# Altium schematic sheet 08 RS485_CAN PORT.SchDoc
size 420 x 297 mm
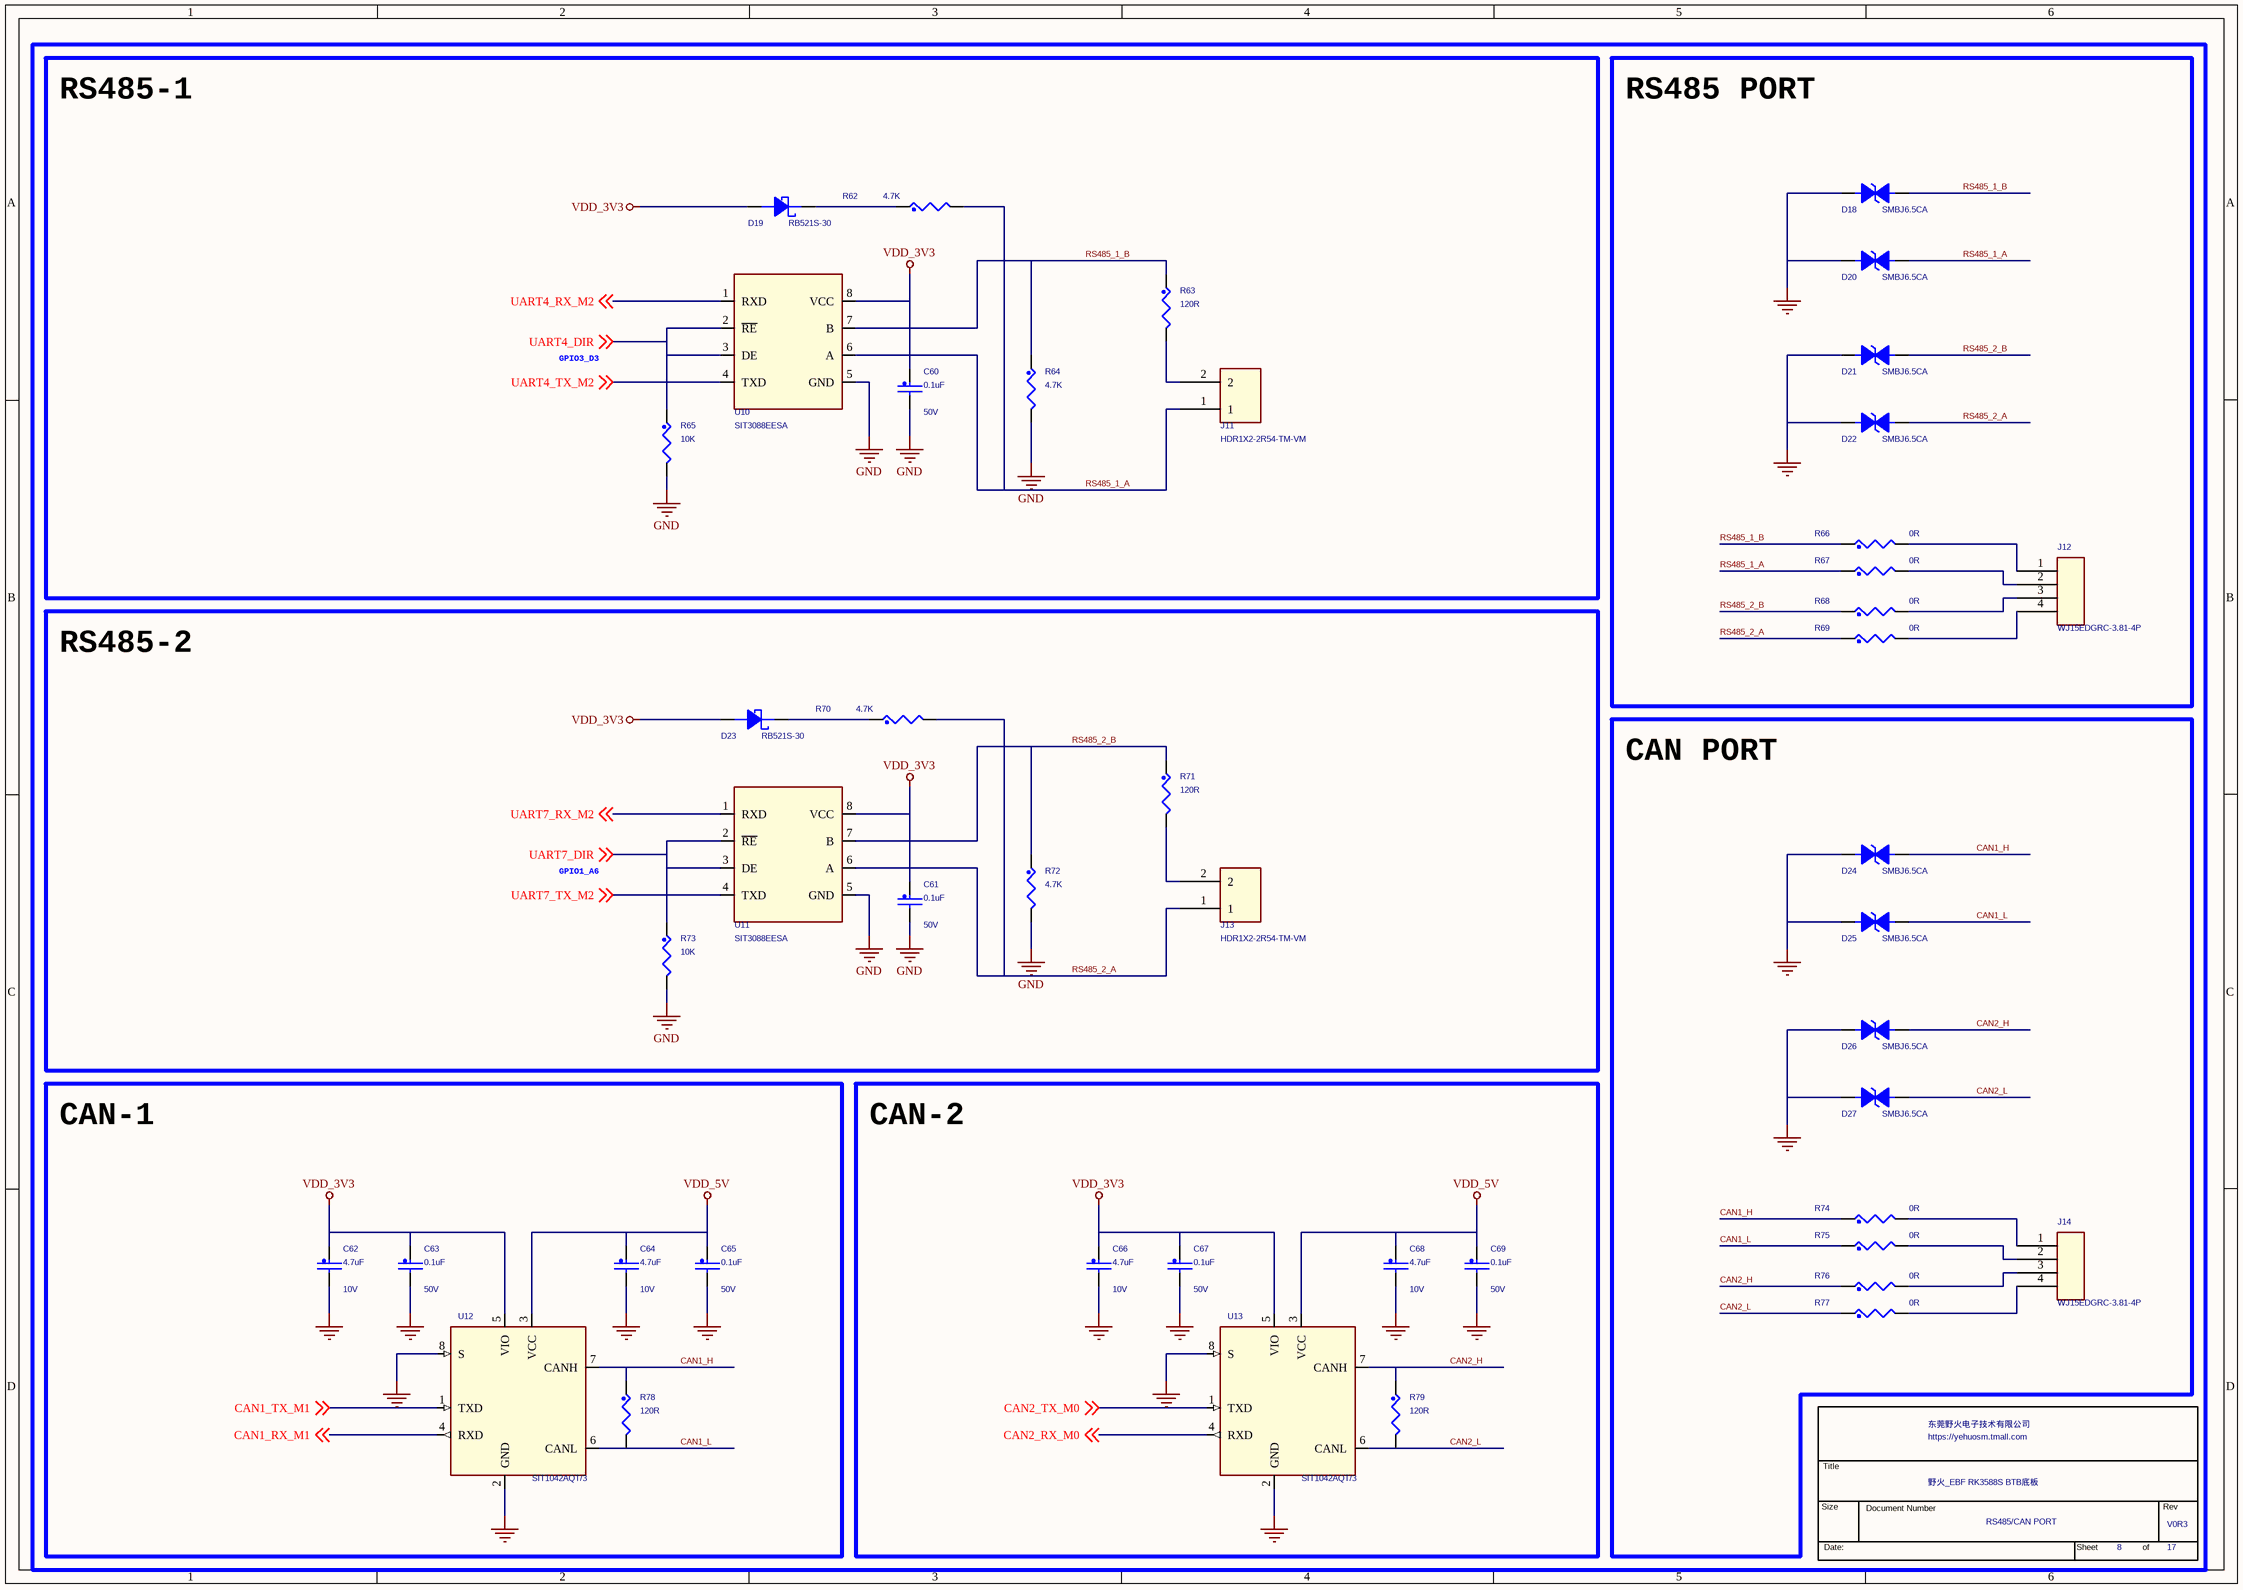
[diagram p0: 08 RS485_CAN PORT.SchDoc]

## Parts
*  Page Count: 17  Page Number: 8  OrgName: 东莞野火电子技术有限公司  Title: 野火_EBF RK3588S BTB底板  RevCode: V0R3  Doc: RS485/CAN PORT  (hidden comment: TitleBlock_YHSCH)  (graphical)
C60  0.1uF  Voltage: 50V  [C0402]
C61  0.1uF  Voltage: 50V  [C0402]
C62  4.7uF  Voltage: 10V  [C0402]
C63  0.1uF  Voltage: 50V  [C0402]
C64  4.7uF  Voltage: 10V  [C0402]
C65  0.1uF  Voltage: 50V  [C0402]
C66  4.7uF  Voltage: 10V  [C0402]
C67  0.1uF  Voltage: 50V  [C0402]
C68  4.7uF  Voltage: 10V  [C0402]
C69  0.1uF  Voltage: 50V  [C0402]
D18  SMBJ6.5CA  [D0603/SMD]
D19  RB521S-30  [SOD523]
D20  SMBJ6.5CA  [D0603/SMD]
D21  SMBJ6.5CA  [D0603/SMD]
D22  SMBJ6.5CA  [D0603/SMD]
D23  RB521S-30  [SOD523]
D24  SMBJ6.5CA  [D0603/SMD]
D25  SMBJ6.5CA  [D0603/SMD]
D26  SMBJ6.5CA  [D0603/SMD]
D27  SMBJ6.5CA  [D0603/SMD]
J11  HDR1X2-2R54-TM-VM  [HDR1X2-2R54-TM-VM]
J12  WJ15EDGRC-3.81-4P  [DB2ERC-3P81-4P]
J13  HDR1X2-2R54-TM-VM  [HDR1X2-2R54-TM-VM]
J14  WJ15EDGRC-3.81-4P  [DB2ERC-3P81-4P]
R62  4.7K  [R0402]
R63  120R  [R0603]
R64  4.7K  [R0402]
R65  10K  [R0402]
R66  0R  [R0603]
R67  0R  [R0603]
R68  0R  [R0603]
R69  0R  [R0603]
R70  4.7K  [R0402]
R71  120R  [R0603]
R72  4.7K  [R0402]
R73  10K  [R0402]
R74  0R  [R0603]
R75  0R  [R0603]
R76  0R  [R0603]
R77  0R  [R0603]
R78  120R  [R0603]
R79  120R  [R0603]
U10  SIT3088EESA  [SOP8]
U11  SIT3088EESA  [SOP8]
U12  SIT1042AQT/3  [SOP8]
U13  SIT1042AQT/3  [SOP8]

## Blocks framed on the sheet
RS485-1: C60 D19 J11 R62-R65 U10
RS485 PORT: D18 D20-D22 J12 R66-R69
RS485-2: C61 D23 J13 R70-R73 U11
CAN PORT: D24-D27 J14 R74-R77
CAN-1: C62-C65 R78 U12
CAN-2: C66-C69 R79 U13

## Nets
GND: C60.2 C61.2 C62.2 C63.2 C64.2 C65.2 C66.2 C67.2 C68.2 C69.2 D18.1 D20.1 D21.1 D22.1 D24.1 D25.1 D26.1 D27.1 R64.2 R65.2 R72.2 R73.2 U10.5(GND) U11.5(GND) U12.2(GND) U12.8(S) U13.2(GND) U13.8(S)
VDD_3V3: C60.1 C61.1 C62.1 C63.1 C66.1 C67.1 D19.2 D23.2 U10.8(VCC) U11.8(VCC) U12.5(VIO) U13.5(VIO)
VDD_5V: C64.1 C65.1 C68.1 C69.1 U12.3(VCC) U13.3(VCC)
CAN1_H: D24.2 R74.1 R78.1 U12.7(CANH)
CAN1_L: D25.2 R75.1 R78.2 U12.6(CANL)
CAN1_RX_M1: U12.4(RXD) ; off-sheet CAN1_RX_M1
CAN1_TX_M1: U12.1(TXD) ; off-sheet CAN1_TX_M1
CAN2_H: D26.2 R76.1 R79.1 U13.7(CANH)
CAN2_L: D27.2 R77.1 R79.2 U13.6(CANL)
CAN2_RX_M0: U13.4(RXD) ; off-sheet CAN2_RX_M0
CAN2_TX_M0: U13.1(TXD) ; off-sheet CAN2_TX_M0
RS485_1_A: D20.2 J11.1 R62.2 R67.1 U10.6(A)
RS485_1_B: D18.2 R63.1 R64.1 R66.1 U10.7(B)
RS485_2_A: D22.2 J13.1 R69.1 R70.2 U11.6(A)
RS485_2_B: D21.2 R68.1 R71.1 R72.1 U11.7(B)
UART4_DIR: R65.1 U10.2(~{RE}) U10.3(DE) ; off-sheet UART4_DIR
UART4_RX_M2: U10.1(RXD) ; off-sheet UART4_RX_M2
UART4_TX_M2: U10.4(TXD) ; off-sheet UART4_TX_M2
UART7_DIR: R73.1 U11.2(~{RE}) U11.3(DE) ; off-sheet UART7_DIR
UART7_RX_M2: U11.1(RXD) ; off-sheet UART7_RX_M2
UART7_TX_M2: U11.4(TXD) ; off-sheet UART7_TX_M2
NetD19_1: D19.1 R62.1
NetD23_1: D23.1 R70.1
NetJ11_2: J11.2 R63.2
NetJ12_1: J12.1 R66.2
NetJ12_2: J12.2 R67.2
NetJ12_3: J12.3 R68.2
NetJ12_4: J12.4 R69.2
NetJ13_2: J13.2 R71.2
NetJ14_1: J14.1 R74.2
NetJ14_2: J14.2 R75.2
NetJ14_3: J14.3 R76.2
NetJ14_4: J14.4 R77.2

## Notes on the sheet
- GPIO3_D3
- GPIO1_A6

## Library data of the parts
* = TitleBlock_YHSCH: Cage Code: 1
C60 C61 C65 C67 = CAP_NP: CLASS: DISCRETE; 规格: 贴片电容0.1uF 10% 50V X5R 0402; 规格编号: 0402X104K500NT; 条码: EBF29060118; 品牌: 风华; 类别: 贴片电容0402; 规格书: 风华电容.pdf; 价格: 0.029826; 生命周期: 量产
C62 C64 = CAP_NP: CLASS: DISCRETE; 生命周期: 量产; 价格: 0.059058; 规格书: 国巨-贴片电容.pdf; 类别: 贴片电容0402; 品牌: 国巨; 条码: EBF29060248; 规格编号: CC0402KRX5R6BB475; 规格: 贴片电容4.7uF 10% 10V X5R 0402
C63 C69 = CAP_NP: CLASS: DISCRETE; 生命周期: 量产; 价格: 0.029826; 规格书: 风华电容.pdf; 类别: 贴片电容0402; 品牌: 风华; 条码: EBF29060118; 规格编号: 0402X104K500NT; 规格: 贴片电容0.1uF 10% 50V X5R 0402
C66 C68 = CAP_NP: CLASS: DISCRETE; 规格: 贴片电容4.7uF 10% 10V X5R 0402; 规格编号: CC0402KRX5R6BB475; 条码: EBF29060248; 品牌: 国巨; 类别: 贴片电容0402; 规格书: 国巨-贴片电容.pdf; 价格: 0.059058; 生命周期: 量产
D18 D20 D22 D24 D26 = DIODE BI-DIR TRIG: 规格: TVS二极管 箝位电压11.2V 击穿电压7.22V 反向关断电压6.5V; 条码: EBF29140023; 品牌: 君耀电子; 类别: 贴片TVS; 规格书: 君耀电子-SMBJ15CA.pdf; 价格: 0.226009; 生命周期: 量产
D19 = DIODE_SCHTKY: CLASS: IC; 生命周期: 量产; 价格: 0.06781; 规格书: 江苏长电_RB521S-30.pdf; 类别: 贴片肖特基二极管; 品牌: 江苏长电; 条码: EBFCIS221114153437; 规格: 直流反向耐压(Vr)：30V 平均整流电流(Io)：200mA 正向压降(Vf)：500mV@200mA 30V@100mA,VF=350mV@10mA
D21 D25 D27 = DIODE BI-DIR TRIG: 生命周期: 量产; 价格: 0.226009; 规格书: 君耀电子-SMBJ15CA.pdf; 类别: 贴片TVS; 品牌: 君耀电子; 条码: EBF29140023; 规格: TVS二极管 箝位电压11.2V 击穿电压7.22V 反向关断电压6.5V
D23 = DIODE_SCHTKY: CLASS: IC; 规格: 直流反向耐压(Vr)：30V 平均整流电流(Io)：200mA 正向压降(Vf)：500mV@200mA 30V@100mA,VF=350mV@10mA; 条码: EBFCIS221114153437; 品牌: 江苏长电; 类别: 贴片肖特基二极管; 规格书: 江苏长电_RB521S-30.pdf; 价格: 0.06781; 生命周期: 量产
J11 = 1X2PIN: 生命周期: 量产; 价格: 0.02; 规格书: 州日_单排针_直插_2P54.pdf; 类别: 2.54mm直插单排排针; 品牌: 州日; 条码: EBF29020019; 规格编号: HDR1X2-2R54-TM-VM-BLUE; 规格: 蓝色直插单排排针 总PIN数2 间距2.54mm
J12 = CON4: 生命周期: 量产; 价格: 0.198381; 规格书: 康奈克斯电气-绿色端子弯针插座.pdf; 类别: 绿色插拔式接线端子; 品牌: 康奈克斯电气; 条码: EBF29040009; 规格: 插拔式接线端子 间距3.81mm 90度弯针 4PIN
J13 = 1X2PIN: 规格: 蓝色直插单排排针 总PIN数2 间距2.54mm; 规格编号: HDR1X2-2R54-TM-VM-BLUE; 条码: EBF29020019; 品牌: 州日; 类别: 2.54mm直插单排排针; 规格书: 州日_单排针_直插_2P54.pdf; 价格: 0.02; 生命周期: 量产
J14 = CON4: 规格: 插拔式接线端子 间距3.81mm 90度弯针 4PIN; 条码: EBF29040009; 品牌: 康奈克斯电气; 类别: 绿色插拔式接线端子; 规格书: 康奈克斯电气-绿色端子弯针插座.pdf; 价格: 0.198381; 生命周期: 量产
R62 R64 R70 R72 = RES: CLASS: DISCRETE; 生命周期: 量产; 规格书: 合科泰-RI系列电阻.pdf; 类别: 贴片电阻0402; 品牌: 合科泰; 条码: EBF29070047; 规格编号: RI0402L4701FT; 规格: 贴片电阻4.7K 1% 1/16W 0402
R63 R71 R78 = RES: CLASS: DISCRETE; 规格: 贴片电阻120R 1% 1/10W 0603; 规格编号: RI0603L1200FT; 条码: EBF29070067; 品牌: 合科泰; 类别: 贴片电阻0603; 规格书: 合科泰-RI系列电阻.pdf; 生命周期: 量产
R65 = RES: CLASS: DISCRETE; 生命周期: 量产; 价格: 0.002773; 规格书: 厚声-无铅厚膜电阻.pdf; 品牌: 厚声; 规格编号: 0402WGF1002TCE; 类别: 贴片电阻0402; 条码: EBF29070046; 规格: 贴片电阻10K 1% 1/16W 0402
R66-R69 = RES: CLASS: DISCRETE; 规格: 贴片电阻0R 1% 1/10W 0603; 规格编号: RI0603L0000FT; 条码: EBF29070063; 品牌: 合科泰; 类别: 贴片电阻0603; 规格书: 合科泰-RI系列电阻.pdf; 生命周期: 量产
R73 = RES: CLASS: DISCRETE; 生命周期: 量产; 价格: 0.002773; 规格书: 厚声-无铅厚膜电阻.pdf; 品牌: 厚声; 规格编号: 0402WGF1002TCE; 规格: 贴片电阻10K 1% 1/16W 0402; 条码: EBF29070046; 类别: 贴片电阻0402
R74-R77 = RES: CLASS: DISCRETE; 生命周期: 量产; 规格书: 合科泰-RI系列电阻.pdf; 类别: 贴片电阻0603; 品牌: 合科泰; 条码: EBF29070063; 规格编号: RI0603L0000FT; 规格: 贴片电阻0R 1% 1/10W 0603
R79 = RES: CLASS: DISCRETE; 生命周期: 量产; 规格书: 合科泰-RI系列电阻.pdf; 类别: 贴片电阻0603; 品牌: 合科泰; 条码: EBF29070067; 规格编号: RI0603L1200FT; 规格: 贴片电阻120R 1% 1/10W 0603
U10 U11 = SIT3088E-8P: CLASS: IC; 规格: RS-485/RS-422芯片 收发器 允许256个器件连接总线 协议类别RS-485 电源电压3.0V~5.5V 数据速率14Mbps; 条码: EBFCIS231207153322; 品牌: 芯力特; 类别: RS485/RS422芯片; 规格书: 芯力特_SIT3088E-V1.8_cn.pdf; 生命周期: 量产; 备注: 鲁班猫
U12 = TJA1057GT3_8P: CLASS: IC; 规格: CAN芯片 收发器 驱动器/接收器数：1/1 协议类别CAN总线 电源电压4.5V~5.5V 数据速率5Mbps; 条码: EBFCIS230524153230; 品牌: 芯力特; 类别: CAN芯片; 规格书: 芯力特_SIT1042.pdf; 价格: 1.98; 生命周期: 量产; 备注: 替代TJA1042T/3/1J
U13 = TJA1057GT3_8P: CLASS: IC; 生命周期: 量产; 价格: 1.98; 规格书: 芯力特_SIT1042.pdf; 类别: CAN芯片; 品牌: 芯力特; 条码: EBFCIS230524153230; 规格: CAN芯片 收发器 驱动器/接收器数：1/1 协议类别CAN总线 电源电压4.5V~5.5V 数据速率5Mbps; 备注: 替代TJA1042T/3/1J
